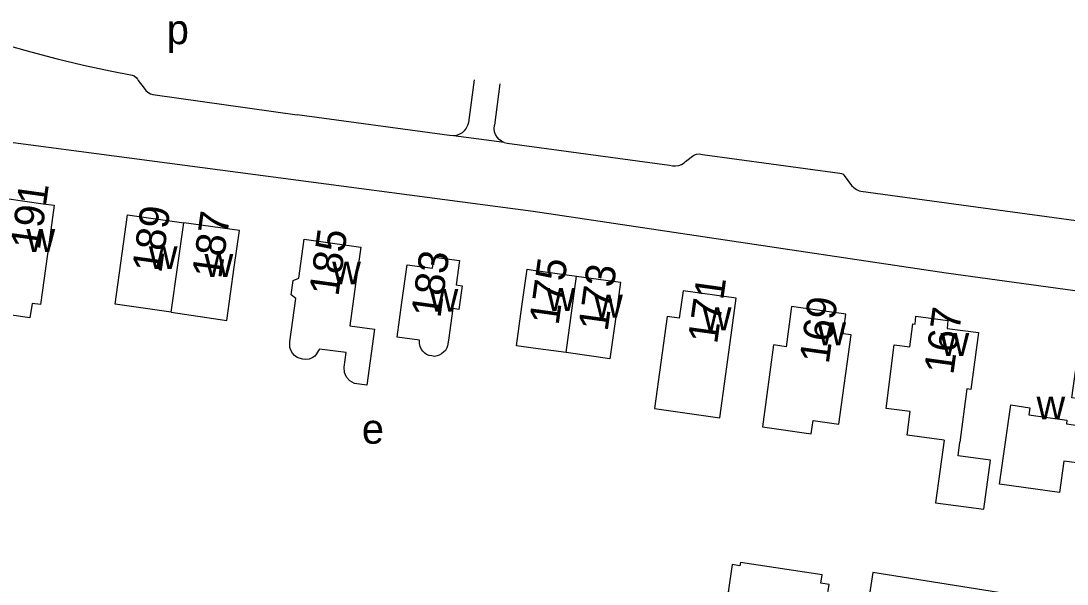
# Model space of a CAD drawing. Extents: x 161093 to 163177, y 379000 to 380904.
# Drawn here: x 161831.1 to 161971.7, y 380742.9 to 380818.6 of the extents above; entities that cross this region are included whole.
import ezdxf

# ---------------------------------------------------------------- set-up
doc = ezdxf.new("R2010")
doc.units = 0
for name, color, linetype in [('BLT_Basislijn', 7, 'Continuous'), ('BLT_Bebouwing', 7, 'Continuous'), ('BLT_Centroide', 7, 'Continuous'), ('BLT_Huisnummer', 7, 'Continuous'), ('BLT_Onderverdeling_panden', 7, 'Continuous')]:
    doc.layers.add(name, color=color, linetype=linetype)

msp = doc.modelspace()

# ---------------------------------------------------------------- linework, layer by layer
at = {"layer": 'BLT_Basislijn'}
for p, q in [((161846.88, 380810.57), (161847.71, 380809.53)), ((161892.04, 380810.66), (161891.27, 380804.94)), ((161895.51, 380810.15), (161894.77, 380804.58)), ((161848.89, 380808.71), (161868.28, 380805.97)), ((161896.09, 380802.27), (161889.27, 380803.15)), ((161920.47, 380799.68), (161921.58, 380800.55)), ((161922.74, 380800.65), (161941.18, 380798.13)), ((161941.79, 380797.8), (161942.77, 380796.49)), ((161944, 380795.73), (161982.7, 380790.46))]:
    msp.add_line(p, q, dxfattribs=at)
for points in [[(161828.95, 380815.42), (161832.46, 380814.42), (161836, 380813.5), (161839.56, 380812.65), (161843.13, 380811.88), (161846.07, 380811.31)], [(161846.07, 380811.31), (161846.36, 380811.19), (161846.61, 380811), (161846.8, 380810.75), (161846.88, 380810.57)], [(161847.71, 380809.53), (161847.93, 380809.23), (161848.21, 380808.99), (161848.54, 380808.81), (161848.89, 380808.71)], [(161889.27, 380803.15), (161888.74, 380803.18), (161868.28, 380805.97)], [(161891.27, 380804.94), (161891.16, 380804.54), (161890.98, 380804.17), (161890.73, 380803.84), (161890.42, 380803.56), (161890.07, 380803.35), (161889.68, 380803.21), (161889.27, 380803.15)], [(161896.09, 380802.27), (161895.72, 380802.44), (161895.4, 380802.67), (161895.13, 380802.97), (161894.92, 380803.32), (161894.79, 380803.7), (161894.73, 380804.09), (161894.77, 380804.58)], [(161815.82, 380804.14), (161900, 380793.04), (161955.5, 380784.75), (162036.45, 380773.62)], [(161896.09, 380802.27), (161896.48, 380802.17), (161918.3, 380799.21)], [(161921.58, 380800.55), (161921.92, 380800.67), (161922.28, 380800.71), (161922.74, 380800.65)], [(161918.3, 380799.21), (161918.7, 380799.12), (161919.12, 380799.11), (161919.54, 380799.17), (161919.93, 380799.31), (161920.29, 380799.53), (161920.47, 380799.68)], [(161941.18, 380798.13), (161941.41, 380798.09), (161941.62, 380797.99), (161941.79, 380797.8)], [(161942.77, 380796.49), (161943.07, 380796.19), (161943.42, 380795.95), (161943.81, 380795.78), (161944, 380795.73)], [(162036.45, 380773.62), (162037.62, 380772.81), (162038.9, 380771.36), (162039.11, 380768.34), (162038.66, 380763.52), (162033.44, 380730.54), (161945.64, 380744.48), (161940.61, 380712.05), (161930.4, 380713.71)]]:
    msp.add_lwpolyline(points, dxfattribs=at)
at = {"layer": 'BLT_Bebouwing'}
for points in [[(161829.19, 380794.74), (161834.14, 380794.02), (161835.63, 380793.82), (161834.94, 380788.86), (161833.78, 380780.49), (161832.63, 380780.64), (161832.36, 380778.71), (161827.04, 380779.46), (161827.88, 380785.42)], [(161851.32, 380779.45), (161843.82, 380780.55), (161844.76, 380787.35), (161845.48, 380792.53), (161853.05, 380791.48)], [(161851.32, 380779.45), (161858.82, 380778.35), (161859.81, 380785.5), (161860.5, 380790.45), (161853.05, 380791.48)], [(161876.12, 380783.24), (161875.35, 380777.64), (161878.68, 380777.18), (161877.63, 380769.65), (161875.97, 380769.88), (161875.35, 380770.23), (161874.88, 380770.75), (161874.63, 380771.35), (161874.58, 380772.08), (161874.85, 380774.02), (161871.25, 380774.51), (161871.14, 380774.31), (161870.87, 380773.86), (161870.62, 380773.56), (161870.29, 380773.31), (161869.9, 380773.14), (161869.45, 380773.08), (161869.01, 380773.13), (161868.53, 380773.26), (161868.28, 380773.38), (161867.9, 380773.66), (161867.65, 380773.95), (161867.45, 380774.28), (161867.26, 380774.7), (161867.26, 380775.11), (161867.28, 380775.49), (161868.09, 380781.3), (161867.46, 380781.79), (161867.73, 380783.72), (161868.49, 380784.03), (161869.22, 380789.25), (161876.81, 380788.2), (161876.12, 380783.24)], [(161890, 380779.84), (161889.18, 380779.96), (161888.59, 380775.72), (161888.48, 380774.92), (161888.36, 380774.65), (161888.18, 380774.33), (161887.98, 380774.12), (161887.68, 380773.86), (161887.36, 380773.68), (161887.06, 380773.58), (161886.7, 380773.52), (161886.36, 380773.58), (161886.02, 380773.63), (161885.66, 380773.79), (161885.44, 380773.96), (161885.17, 380774.21), (161884.99, 380774.46), (161884.8, 380774.86), (161884.71, 380775.27), (161884.72, 380775.68), (161881.69, 380776.1), (161882.34, 380780.78), (161883.04, 380785.84), (161886.46, 380785.36), (161886.67, 380786.87), (161890.08, 380786.4), (161889.62, 380783.11), (161890.44, 380783), (161890, 380779.84)], [(161904.4, 380774.02), (161900, 380774.63), (161897.74, 380774.95), (161898.47, 380780.24), (161899.16, 380785.23), (161900, 380785.11), (161905.82, 380784.31)], [(161905.82, 380784.31), (161911.73, 380783.49), (161911.04, 380778.54), (161910.3, 380773.21), (161904.4, 380774.02)], [(161926.58, 380776.38), (161927.27, 380781.33), (161920.13, 380782.32), (161919.62, 380778.65), (161918, 380778.88), (161916.27, 380766.5), (161925.05, 380765.28), (161926.58, 380776.38)], [(161933.98, 380774.82), (161932.27, 380775.06), (161930.8, 380764.06), (161937.35, 380763.12), (161937.6, 380764.9), (161941.05, 380764.42), (161942.73, 380776.41), (161941.62, 380776.55), (161941.99, 380779.21), (161934.72, 380780.22), (161933.98, 380774.82)], [(161955.21, 380762.28), (161950.24, 380762.95), (161950.65, 380766.11), (161947.4, 380766.54), (161948.51, 380775.09), (161950.58, 380774.79), (161951, 380777.9), (161951.3, 380777.86), (161951.43, 380778.91), (161955.73, 380778.33), (161955.6, 380777.28), (161959.81, 380776.71), (161958.81, 380769.07), (161958.25, 380769.14), (161957.34, 380761.99)], [(161971.71, 380764.94), (161971.64, 380764.44), (161973.22, 380764.22), (161973.72, 380767.78), (161972.39, 380767.97), (161972.57, 380769.23), (161973.26, 380774.23), (161977.2, 380773.68), (161977.31, 380774.48), (161980.93, 380773.99)], [(161971.3, 380759.44), (161970.71, 380755.22), (161962.67, 380756.34), (161964.16, 380766.99), (161966.72, 380766.63), (161966.58, 380765.65), (161971.71, 380764.94)], [(161955.21, 380762.28), (161954.06, 380753.87), (161960.55, 380752.99), (161961.43, 380759.58), (161957.1, 380760.16), (161957.34, 380761.99)], [(161979.24, 380761.24), (161976.12, 380761.68), (161975.95, 380760.42), (161973.27, 380760.79), (161973.05, 380759.2), (161971.3, 380759.44)], [(161931.56, 380732.27), (161932.44, 380737.95), (161938.83, 380736.97), (161939.75, 380742.9), (161938.65, 380743.07), (161938.82, 380744.16), (161927.83, 380745.85), (161927.76, 380745.39), (161926.73, 380745.55), (161926.17, 380741.86), (161926.37, 380741.83), (161925.97, 380739.25), (161922.98, 380739.71), (161922.24, 380734.87)]]:
    msp.add_lwpolyline(points, dxfattribs=at)
at = {"layer": 'BLT_Onderverdeling_panden'}
for p, q in [((161851.32, 380779.45), (161853.05, 380791.48)), ((161904.4, 380774.02), (161905.82, 380784.31))]:
    msp.add_line(p, q, dxfattribs=at)

# ---------------------------------------------------------------- texts
at = {"layer": 'BLT_Centroide'}
for s, p in [('p', (161850.74, 380815.46)), ('w', (161831.88, 380787.55)), ('w', (161848.33, 380785.25)), ('w', (161855.81, 380784.19)), ('w', (161872.97, 380783.19)), ('w', (161886.06, 380779.52)), ('w', (161901.78, 380779.62)), ('w', (161908.17, 380778.73)), ('w', (161922.77, 380777.02)), ('w', (161938.17, 380775.02)), ('w', (161954.72, 380773.59)), ('w', (161967.62, 380765.06)), ('e', (161876.96, 380761.79))]:
    msp.add_text(s, height=4, dxfattribs=at).set_placement(p)
at = {"layer": 'BLT_Huisnummer'}
for s, rotation, p in [('191', 82.1094, (161833.68, 380787.72)), ('189', 82.0849, (161850.02, 380784.62)), ('187', 82.113, (161858.06, 380783.85)), ('185', 82.1017, (161873.8, 380781.49)), ('183', 82.1166, (161887.51, 380778.58)), ('175', 82.1031, (161903.39, 380777.61)), ('173', 82.1017, (161909.98, 380776.78)), ('171', 82.1014, (161924.7, 380775.09)), ('169', 82.113, (161939.7, 380772.41)), ('167', 82.113, (161956.44, 380770.96))]:
    msp.add_text(s, height=4, rotation=rotation, dxfattribs=at).set_placement(p)

doc.saveas('drawing.dxf')
